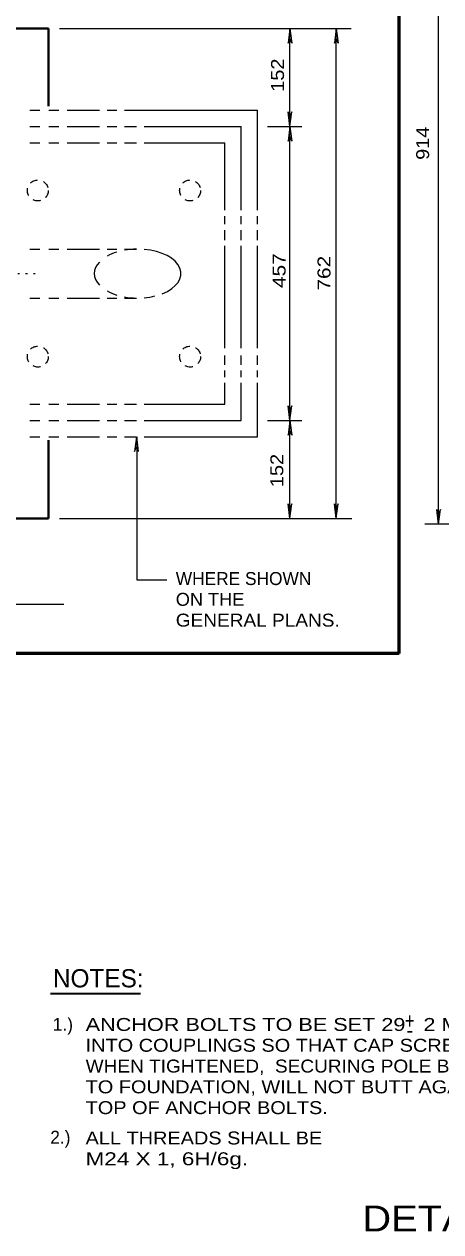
# Model space of a CAD drawing. Extents: x 312583 to 312854, y 144419 to 144597.
# Drawn here: x 312667.9 to 312692.4, y 144489.4 to 144560.3 of the extents above; entities that cross this region are included whole.
import ezdxf
from ezdxf.enums import TextEntityAlignment as Align

# ---------------------------------------------------------------- set-up
doc = ezdxf.new("R2010")
doc.units = 0
doc.header["$LTSCALE"] = 0.3
doc.linetypes.add('DOTTED', pattern=[1.5, 0.3, -1.2])
doc.linetypes.add('SHORT_DASHED', pattern=[2.7, 1.5, -1.2])
doc.layers.add('1', color=7, linetype='Continuous', lineweight=13)

msp = doc.modelspace()

# ---------------------------------------------------------------- linework, layer by layer
at = {"layer": '1', "lineweight": 53}
for q in [(312689.9495, 144585.0846), (312666.9226, 144523.38)]:
    msp.add_line((312689.9495, 144523.38), q, dxfattribs=at)
at = {"layer": '1'}
for p, q in [((312692.262, 144530.9681), (312692.262, 144574.2925)), ((312683.5296, 144560.0535), (312683.4223, 144559.1872)), ((312683.4223, 144559.1872), (312683.5296, 144559.4632)), ((312683.5296, 144560.0535), (312683.6369, 144559.1872)), ((312683.6369, 144559.1872), (312683.5296, 144559.4632)), ((312686.2589, 144560.0535), (312686.1516, 144559.1872)), ((312686.1516, 144559.1872), (312686.2589, 144559.4632)), ((312686.2589, 144531.3035), (312686.2589, 144560.0535)), ((312686.2589, 144560.0535), (312686.3663, 144559.1872)), ((312686.3663, 144559.1872), (312686.2589, 144559.4632)), ((312683.4223, 144555.1699), (312683.5296, 144554.8939)), ((312683.5296, 144554.3035), (312683.4223, 144555.1699)), ((312683.6369, 144555.1699), (312683.5296, 144554.8939)), ((312683.5296, 144554.3035), (312683.6369, 144555.1699)), ((312682.2092, 144554.3035), (312684.2349, 144554.3035)), ((312683.5296, 144554.3035), (312683.4223, 144553.4372)), ((312683.4223, 144553.4372), (312683.5296, 144553.7132)), ((312683.5296, 144554.3035), (312683.6369, 144553.4372)), ((312683.6369, 144553.4372), (312683.5296, 144553.7132)), ((312683.4223, 144537.9199), (312683.5296, 144537.6439)), ((312683.5296, 144537.0535), (312683.4223, 144537.9199)), ((312683.6369, 144537.9199), (312683.5296, 144537.6439)), ((312683.5296, 144537.0535), (312683.6369, 144537.9199)), ((312682.2092, 144537.0535), (312684.2349, 144537.0535)), ((312683.5296, 144537.0535), (312683.4223, 144536.1872)), ((312683.5296, 144537.0535), (312683.6369, 144536.1872)), ((312674.5205, 144536.0952), (312674.4131, 144535.2289)), ((312674.5205, 144536.0952), (312674.6278, 144535.2289)), ((312683.4223, 144536.1872), (312683.5296, 144536.4632)), ((312683.6369, 144536.1872), (312683.5296, 144536.4632)), ((312674.4131, 144535.2289), (312674.5205, 144535.5049)), ((312674.6278, 144535.2289), (312674.5205, 144535.5049)), ((312683.4223, 144532.1622), (312683.5296, 144531.8862)), ((312683.5296, 144531.2959), (312683.4223, 144532.1622)), ((312683.6369, 144532.1622), (312683.5296, 144531.8862)), ((312683.5296, 144531.2959), (312683.6369, 144532.1622)), ((312686.1516, 144532.1699), (312686.2589, 144531.8939)), ((312686.2589, 144531.3035), (312686.1516, 144532.1699)), ((312686.3663, 144532.1699), (312686.2589, 144531.8939)), ((312686.2589, 144531.3035), (312686.3663, 144532.1699)), ((312692.1547, 144531.8345), (312692.262, 144531.5585)), ((312692.262, 144530.9681), (312692.1547, 144531.8345)), ((312692.3694, 144531.8345), (312692.262, 144531.5585)), ((312692.262, 144530.9681), (312692.3694, 144531.8345)), ((312695.2904, 144530.9681), (312691.457, 144530.9681)), ((312667.0627, 144526.2742), (312670.2597, 144526.2742))]:
    msp.add_line(p, q, dxfattribs=at)
at = {"layer": '1', "lineweight": 40}
for p, q in [((312669.3589, 144560.0535), (312669.3589, 144555.5072)), ((312669.3589, 144535.9035), (312669.3589, 144531.3035))]:
    msp.add_line(p, q, dxfattribs=at)
at = {"layer": '1', "lineweight": 25}
for p, q in [((312668.2549, 144555.2619), (312668.8452, 144555.2619)), ((312669.3666, 144555.2619), (312669.9569, 144555.2619)), ((312672.7955, 144555.2619), (312673.3628, 144555.2619)), ((312673.8151, 144555.2619), (312681.6275, 144555.2619)), ((312681.6275, 144549.3892), (312681.6275, 144555.2619)), ((312668.2549, 144554.3035), (312668.8452, 144554.3035)), ((312669.3666, 144554.3035), (312669.9569, 144554.3035)), ((312672.7955, 144554.3035), (312673.3628, 144554.3035)), ((312673.8151, 144554.3035), (312674.5205, 144554.3035)), ((312674.9728, 144554.3035), (312680.6691, 144554.3035)), ((312680.6691, 144549.3892), (312680.6691, 144554.3035)), ((312668.2549, 144553.3452), (312668.8452, 144553.3452)), ((312669.3666, 144553.3452), (312669.9569, 144553.3452)), ((312672.7955, 144553.3452), (312673.3628, 144553.3452)), ((312673.8151, 144553.3452), (312674.5205, 144553.3452)), ((312674.9728, 144553.3452), (312679.7108, 144553.3452)), ((312679.7108, 144549.3892), (312679.7108, 144553.3452)), ((312679.7108, 144548.5765), (312679.7108, 144549.0519)), ((312680.6691, 144548.5765), (312680.6691, 144549.0519)), ((312681.6275, 144548.5765), (312681.6275, 144549.0519)), ((312679.7108, 144547.6412), (312679.7108, 144548.2315)), ((312680.6691, 144547.6412), (312680.6691, 144548.2315)), ((312681.6275, 144547.6412), (312681.6275, 144548.2315)), ((312668.2549, 144547.1122), (312668.8452, 144547.1122)), ((312669.3666, 144547.1122), (312669.9569, 144547.1122)), ((312672.7955, 144547.1122), (312673.3628, 144547.1122)), ((312673.8151, 144547.1122), (312674.5205, 144547.1122)), ((312679.7108, 144541.3009), (312679.7108, 144547.3039)), ((312680.6691, 144541.3009), (312680.6691, 144547.3039)), ((312681.6275, 144541.3009), (312681.6275, 144547.3039)), ((312668.2549, 144544.2372), (312668.8452, 144544.2372)), ((312669.3666, 144544.2372), (312669.9569, 144544.2372)), ((312672.7955, 144544.2372), (312673.3628, 144544.2372)), ((312673.8151, 144544.2372), (312674.5205, 144544.2372)), ((312679.7108, 144540.3272), (312679.7108, 144540.8715)), ((312680.6691, 144540.3272), (312680.6691, 144540.8715)), ((312681.6275, 144540.3272), (312681.6275, 144540.8715)), ((312679.7108, 144539.5989), (312679.7108, 144539.9822)), ((312680.6691, 144539.5989), (312680.6691, 144539.9822)), ((312681.6275, 144539.5989), (312681.6275, 144539.9822)), ((312679.7108, 144538.0119), (312679.7108, 144539.2615)), ((312680.6691, 144537.0535), (312680.6691, 144539.2615)), ((312681.6275, 144536.0952), (312681.6275, 144539.2615)), ((312668.2549, 144538.0119), (312668.8452, 144538.0119)), ((312669.3666, 144538.0119), (312669.9569, 144538.0119)), ((312672.7955, 144538.0119), (312673.3628, 144538.0119)), ((312673.8151, 144538.0119), (312674.5205, 144538.0119)), ((312674.9728, 144538.0119), (312679.7108, 144538.0119)), ((312668.2549, 144537.0535), (312668.8452, 144537.0535)), ((312669.3666, 144537.0535), (312669.9569, 144537.0535)), ((312672.7955, 144537.0535), (312673.3628, 144537.0535)), ((312673.8151, 144537.0535), (312674.5205, 144537.0535)), ((312674.9728, 144537.0535), (312680.6691, 144537.0535)), ((312668.2549, 144536.0952), (312668.8452, 144536.0952)), ((312669.3666, 144536.0952), (312669.9569, 144536.0952)), ((312672.7955, 144536.0952), (312673.3628, 144536.0952)), ((312673.8151, 144536.0952), (312674.5205, 144536.0952)), ((312674.9728, 144536.0952), (312681.6275, 144536.0952))]:
    msp.add_line(p, q, dxfattribs=at)
at = {"layer": '1', "lineweight": 35}
msp.add_line((312669.4765, 144503.4346), (312674.7668, 144503.4346), dxfattribs=at)
at = {"layer": '1', "lineweight": 40}
for points in [[(312637.9923, 144560.0535), (312662.0319, 144560.0535), (312669.3589, 144560.0535)], [(312658.89, 144531.3035), (312662.0319, 144531.3035), (312669.3589, 144531.3035)]]:
    msp.add_lwpolyline(points, dxfattribs=at)
at = {"layer": '1'}
for points in [[(312670.0029, 144560.0535), (312682.2092, 144560.0535), (312687.1333, 144560.0535)], [(312683.5296, 144531.2959), (312683.5296, 144537.0535), (312683.5296, 144554.3035), (312683.5296, 144560.0535)], [(312674.5454, 144536.0952), (312674.5454, 144527.7079), (312676.3087, 144527.7079)], [(312670.0029, 144531.3035), (312682.2092, 144531.3035), (312687.1793, 144531.3035)]]:
    msp.add_lwpolyline(points, dxfattribs=at)
at = {"layer": '1', "lineweight": 25}
for points in [[(312670.4552, 144555.2619), (312671.7758, 144555.2619), (312672.3431, 144555.2619)], [(312670.4552, 144554.3035), (312671.7758, 144554.3035), (312672.3431, 144554.3035)], [(312670.4552, 144553.3452), (312671.7758, 144553.3452), (312672.3431, 144553.3452)], [(312670.4552, 144547.1122), (312671.7758, 144547.1122), (312672.3431, 144547.1122)], [(312670.4552, 144544.2372), (312671.7758, 144544.2372), (312672.3431, 144544.2372)], [(312670.4552, 144538.0119), (312671.7758, 144538.0119), (312672.3431, 144538.0119)], [(312670.4552, 144537.0535), (312671.7758, 144537.0535), (312672.3431, 144537.0535)], [(312670.4552, 144536.0952), (312671.7758, 144536.0952), (312672.3431, 144536.0952)]]:
    msp.add_lwpolyline(points, dxfattribs=at)
at = {"layer": '1', "linetype": 'DOTTED'}
msp.add_lwpolyline([(312649.9277, 144545.6785), (312662.0319, 144545.6785), (312668.7072, 144545.6785)], dxfattribs=at)
at = {"layer": '1', "linetype": 'SHORT_DASHED', "lineweight": 25}
for centre in [(312668.7293, 144550.5517), (312677.6705, 144550.5517), (312668.7293, 144540.8016), (312677.6705, 144540.8016)]:
    msp.add_circle(centre, 0.6152, dxfattribs=at)
at = {"layer": '1', "lineweight": 25}
for start_param, end_param in [(2.0727204, 2.3502038), (1.5971705, 1.8781954), (5.3189382, 7.7014173), (2.6514507, 3.6323236), (3.9335562, 4.2108724), (4.4049772, 4.6860042), (4.8648407, 5.1250175)]:
    msp.add_ellipse((312674.5875, 144545.6766), major_axis=(2.5458, 0), ratio=0.564653, start_param=start_param, end_param=end_param, dxfattribs=at)

# ---------------------------------------------------------------- texts
at = {"layer": '1'}
for s, width, p in [('152 ', 1.15, (312683.1862, 144556.3426)), ('914 ', 1.15, (312691.7084, 144552.3462)), ('457 ', 1.2, (312683.278, 144544.8285)), ('762 ', 1.2, (312685.9154, 144544.6808)), ('152 ', 1.15, (312683.1442, 144533.1448))]:
    msp.add_text(s, height=0.76, rotation=90, dxfattribs=dict(at, width=width)).set_placement(p)
for s, p in [('WHERE SHOWN', (312676.83, 144527.4002)), ('1.)   ', (312669.6083, 144501.2422)), ('2.)  ', (312669.4588, 144494.6173))]:
    msp.add_text(s, height=0.76, dxfattribs=at).set_placement(p)
for s, width, p in [('ON THE', 1.05, (312676.83, 144526.1802)), ('GENERAL PLANS.', 1.1, (312676.83, 144524.9602)), ('ANCHOR BOLTS TO BE SET 29   2 MM', 1.25, (312671.5374, 144501.2346)), ('INTO COUPLINGS SO THAT CAP SCREWS', 1.15, (312671.5374, 144500.0146)), ('WHEN TIGHTENED,  SECURING POLE BASE', 1.1, (312671.5374, 144498.7946)), ('TO FOUNDATION, WILL NOT BUTT AGAINST', 1.15, (312671.5374, 144497.5746)), ('TOP OF ANCHOR BOLTS.', 1.15, (312671.5374, 144496.3546)), ('ALL THREADS SHALL BE', 1.15, (312671.5324, 144494.574)), ('M24 X 1, 6H/6g.', 1.3, (312671.5324, 144493.354))]:
    msp.add_text(s, height=0.76, dxfattribs=dict(at, width=width)).set_placement(p)
for s, height, p in [('NOTES:', 1.07, (312672.2782, 144503.7927)), ('-', 0.92, (312690.5715, 144500.8322))]:
    msp.add_text(s, height=height, dxfattribs=at).set_placement(p, align=Align.CENTER)
for s, height, width, p in [('+', 0.92, 0.8, (312690.5639, 144501.3765)), ('DETAIL OF ANCHOR BOLTS', 1.52, 1.15, (312703.3752, 144489.4688))]:
    msp.add_text(s, height=height, dxfattribs=dict(at, width=width)).set_placement(p, align=Align.CENTER)

doc.saveas('drawing.dxf')
